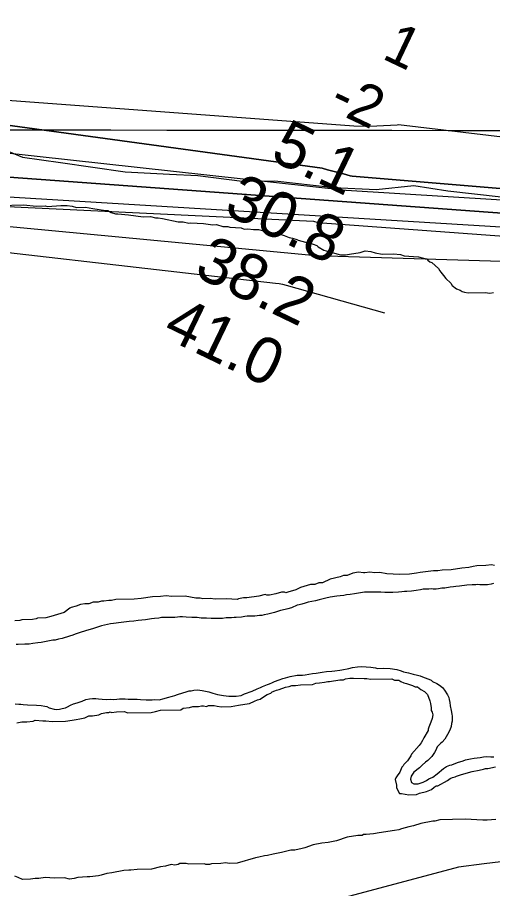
# Model space of a CAD drawing. Extents: x 3219052 to 3256913, y 800770 to 826146.
# Drawn here: x 3235776 to 3236468, y 811124 to 812391 of the extents above; entities that cross this region are included whole.
import ezdxf

# ---------------------------------------------------------------- set-up
doc = ezdxf.new("R2010")
doc.units = 0
for name, color, linetype in [('V-GRID-MAJR', 7, 'Continuous'), ('V-LEVE-TOET', 7, 'Continuous'), ('V-RIVR-EDGE', 7, 'Continuous'), ('V-RIVR-RANG', 7, 'Continuous'), ('V-SITE-VEGE', 7, 'Continuous'), ('V-TOPO-DPTH', 7, 'Continuous'), ('V-TOPO-MAJR', 7, 'Continuous'), ('V-TOPO-MINR', 7, 'Continuous'), ('V-TOPO-SHOR', 7, 'Continuous'), ('V-TOPO-WATR', 7, 'Continuous')]:
    doc.layers.add(name, color=color, linetype=linetype)

msp = doc.modelspace()

# ---------------------------------------------------------------- linework, layer by layer
at = {"layer": 'V-GRID-MAJR'}
msp.add_spline([(3223229.222, 812245.659), (3228465.955, 812237.661), (3233702.6890000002, 812230.425), (3238939.4250000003, 812223.951), (3244176.161, 812218.238), (3249412.899, 812213.287), (3254649.637, 812209.098), (3254649.6380000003, 812209.098)], degree=3, dxfattribs=at)
at = {"layer": 'V-LEVE-TOET'}
msp.add_lwpolyline([(3238182.165, 811071.7000000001), (3237860.271, 811198.746), (3237814.414, 811217.536), (3237784.448, 811226.4720000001), (3237756.583, 811232.116), (3237732.015, 811236.265), (3237708.346, 811240.419), (3237688.88, 811239.188), (3237662.825, 811237.3470000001), (3237316.042, 811205.908), (3236864.697, 811191.961), (3236556.232, 811171.966), (3236455.3140000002, 811160.1140000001), (3236418.184, 811154.96), (3236209.219, 811099.193)], dxfattribs=at)
at = {"layer": 'V-RIVR-EDGE'}
msp.add_lwpolyline([(3235755.3521574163, 812199.8585702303), (3235783.577111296, 812188.0524400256), (3235838.761683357, 812180.0917591), (3235933.054244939, 812166.8182251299), (3235997.377772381, 812163.1817380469), (3236038.6677431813, 812161.3409230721), (3236103.4141240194, 812152.9219193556), (3236150.7960151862, 812153.6741159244), (3236236.838321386, 812143.8984159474), (3236298.1212627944, 812141.1388057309), (3236352.9044780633, 812146.6541719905), (3236402.439330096, 812139.1421403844), (3236480.224931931, 812130.2562152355)], dxfattribs=at)
at = {"layer": 'V-SITE-VEGE'}
for points in [[(3235749.586, 812117.927), (3235785.686, 812118.613), (3235803.262, 812116.883), (3235816.67, 812117.139), (3235819.7830000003, 812116.166), (3235839.362, 812117.571), (3235848.648, 812117.747), (3235855.8850000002, 812116.8520000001), (3235862.113, 812114.906), (3235875.524, 812115.162), (3235885.876, 812113.2930000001), (3235904.503, 812110.552), (3235907.597, 812110.61), (3235912.8140000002, 812107.615), (3235919.042, 812105.672), (3235922.134, 812105.729), (3235937.646, 812103.962), (3235959.367, 812101.279), (3235969.68, 812101.474), (3235976.941, 812099.5480000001), (3235981.065, 812099.626), (3235987.275, 812098.711), (3236010.063, 812093.986), (3236017.284, 812094.123), (3236025.576, 812092.219), (3236028.671, 812092.278), (3236047.257, 812091.598), (3236060.7060000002, 812089.792), (3236065.863, 812089.888), (3236075.204, 812086.9720000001), (3236082.4250000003, 812087.109), (3236085.542, 812086.134), (3236102.059, 812085.417), (3236106.227, 812083.433), (3236111.384, 812083.531), (3236119.653, 812082.656), (3236126.877, 812082.794), (3236134.1350000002, 812080.8690000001), (3236157.957, 812076.162), (3236164.185, 812074.2170000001), (3236171.464, 812071.259), (3236176.6410000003, 812070.3250000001), (3236182.869, 812068.382), (3236184.952, 812067.389), (3236195.325, 812064.491), (3236203.615, 812062.584), (3236206.732, 812061.611), (3236211.926, 812059.649), (3236214.029, 812057.6240000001), (3236222.379, 812052.623), (3236225.494, 812051.65), (3236246.24, 812045.854), (3236253.461, 812045.991), (3236259.628, 812047.14), (3236275.062, 812049.497), (3236282.242, 812051.697), (3236290.5160000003, 812050.822), (3236296.744, 812048.877), (3236307.097, 812047.009), (3236323.599, 812047.324), (3236333.934, 812046.4890000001), (3236339.131, 812044.525), (3236352.558, 812043.747), (3236359.802, 812042.854), (3236367.06, 812040.926), (3236372.237, 812039.997), (3236373.306, 812037.951), (3236376.4420000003, 812035.948), (3236379.555, 812034.975), (3236389.015, 812025.868), (3236391.136, 812022.812), (3236392.205, 812020.768), (3236396.43, 812015.693), (3236399.603, 812011.6240000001), (3236406.961, 812004.5380000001), (3236409.083, 812001.484), (3236415.3680000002, 811996.446), (3236420.566, 811994.48), (3236423.699, 811992.4770000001), (3236426.812, 811991.502), (3236431.99, 811990.5700000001), (3236456.748, 811991.039), (3236463.986, 811990.1460000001), (3236469.124, 811991.277)], [(3236470.484, 811594.0430000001), (3236466.339, 811594.997), (3236458.108, 811593.807), (3236444.698, 811593.5530000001), (3236439.559, 811592.4230000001), (3236433.3910000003, 811591.274), (3236423.095, 811590.047), (3236407.664, 811587.6900000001), (3236394.253, 811587.434), (3236388.085, 811586.285), (3236381.896, 811586.1680000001), (3236362.3370000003, 811583.733), (3236357.199, 811582.6020000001), (3236346.904, 811581.376), (3236332.463, 811581.099), (3236313.875, 811581.779), (3236303.525, 811583.647), (3236296.304, 811583.508), (3236289.0640000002, 811584.403), (3236281.863, 811583.235), (3236279.801, 811583.194), (3236272.559, 811584.089), (3236264.328, 811582.899), (3236256.134, 811579.649), (3236250.977, 811579.551), (3236245.859, 811577.39), (3236231.478, 811574.0210000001), (3236220.231, 811568.647), (3236215.072, 811568.549), (3236208.924, 811566.37), (3236202.737, 811566.251), (3236188.372, 811561.85), (3236181.21, 811558.62), (3236169.924, 811555.311), (3236166.847, 811554.2170000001), (3236164.767, 811555.213), (3236160.64, 811555.133), (3236152.43, 811552.9130000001), (3236143.185, 811550.674), (3236139.056, 811550.594), (3236136.975, 811551.588), (3236127.731, 811549.3470000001), (3236110.235, 811546.953), (3236105.078, 811546.855), (3236097.877, 811545.685), (3236095.833, 811544.6140000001), (3236080.342, 811545.351), (3236063.839, 811545.0380000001), (3236056.6, 811545.931), (3236046.284, 811545.736), (3236042.139, 811546.689), (3236035.948, 811546.572), (3236020.42, 811549.372), (3236000.818, 811549.001), (3235992.5500000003, 811549.873), (3235984.3170000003, 811548.686), (3235972.972, 811548.471), (3235956.506, 811546.093), (3235946.2120000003, 811544.8640000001), (3235919.394, 811544.356), (3235913.225, 811543.2050000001), (3235909.098, 811543.127), (3235901.898, 811541.96), (3235898.805, 811541.9010000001), (3235893.667, 811540.768), (3235886.446, 811540.635), (3235880.295, 811538.454), (3235874.106, 811538.335), (3235867.938, 811537.186), (3235861.79, 811535.007), (3235854.607, 811532.805), (3235852.563, 811531.732), (3235844.431, 811525.39), (3235824.93, 811519.86), (3235817.749, 811517.66), (3235805.3710000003, 811517.425), (3235803.327, 811516.354)], [(3235803.327, 811516.354), (3235798.191, 811515.223), (3235782.718, 811514.9280000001), (3235779.644, 811513.839), (3235772.423, 811513.702)], [(3236114.1890000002, 811393.283), (3236121.349, 811396.513), (3236125.437, 811398.655), (3236129.543, 811399.765), (3236131.585, 811400.836), (3236139.74, 811406.1510000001), (3236144.858, 811408.312), (3236146.879, 811410.415), (3236150.988, 811411.525), (3236153.032, 811412.594), (3236157.1380000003, 811413.706), (3236166.362, 811416.975), (3236171.501, 811418.105), (3236175.607, 811419.215), (3236180.764, 811419.313), (3236187.964, 811420.481), (3236205.499, 811420.8150000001), (3236210.617, 811422.975), (3236215.774, 811423.074), (3236222.975, 811424.243), (3236228.111, 811425.371), (3236230.176, 811425.41), (3236245.609, 811427.768), (3236250.7660000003, 811427.866), (3236253.84, 811428.957), (3236260.011, 811430.106), (3236265.168, 811430.2050000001), (3236280.659, 811429.4670000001), (3236284.786, 811429.545), (3236289.963, 811428.611), (3236320.906, 811429.199), (3236325.072, 811427.215), (3236331.2630000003, 811427.333), (3236334.394, 811425.328), (3236338.558, 811423.346), (3236342.703, 811422.392), (3236351.014, 811419.4550000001), (3236355.18, 811417.468), (3236358.274, 811417.528), (3236363.511, 811413.4990000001), (3236368.725, 811410.505), (3236372.93, 811406.456), (3236376.2, 811397.232), (3236377.31, 811393.126), (3236378.4590000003, 811386.957), (3236378.539, 811382.8300000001), (3236379.608, 811380.7880000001), (3236380.718, 811376.68), (3236379.786, 811371.505), (3236377.8200000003, 811366.307), (3236374.865, 811359.028), (3236373.89, 811355.916), (3236373.931, 811353.851), (3236367.9390000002, 811343.419), (3236365.952, 811339.255), (3236363.949, 811336.122), (3236360.932, 811331.938), (3236349.822, 811319.3420000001), (3236348.8310000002, 811317.26), (3236346.826, 811314.126), (3236343.809, 811309.942), (3236338.75, 811304.687), (3236337.757, 811302.604), (3236335.734, 811300.503), (3236332.778, 811293.2220000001), (3236328.75, 811287.987), (3236326.745, 811284.854), (3236325.754, 811282.7710000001), (3236327.974, 811274.559), (3236328.052, 811270.432), (3236332.3340000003, 811262.258), (3236335.429, 811262.318), (3236345.7830000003, 811260.4500000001), (3236357.129, 811260.667), (3236361.215, 811262.807), (3236371.492, 811265.066), (3236378.6520000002, 811268.3), (3236382.719, 811271.4720000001), (3236385.773, 811273.5920000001), (3236387.839, 811273.633), (3236402.14, 811281.127), (3236406.207, 811284.299), (3236409.284, 811285.3910000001), (3236413.39, 811286.501), (3236415.432, 811287.572), (3236422.614, 811289.7710000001), (3236438.007, 811294.191), (3236448.282, 811296.448), (3236454.452, 811297.601), (3236457.526, 811298.6900000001), (3236460.6210000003, 811298.75), (3236471.928, 811301.027)], [(3235775.247, 811365.17), (3235782.448, 811366.34), (3235789.667, 811366.475), (3235798.932, 811367.683), (3235802.004, 811368.775), (3235813.373, 811367.958), (3235817.498, 811368.0380000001), (3235826.802, 811367.182), (3235846.399, 811367.554), (3235855.662, 811368.763), (3235861.833, 811369.912), (3235866.969, 811371.04), (3235874.17, 811372.209), (3235880.3000000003, 811375.4230000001), (3235885.4560000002, 811375.5210000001), (3235894.722, 811376.725), (3235898.807, 811378.8690000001), (3235906.008, 811380.039), (3235909.103, 811380.094), (3235911.146, 811381.167), (3235913.2290000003, 811380.176), (3235920.428, 811381.343), (3235931.776, 811381.561), (3235936.972, 811379.594), (3235971.012, 811380.242), (3235977.18, 811381.3910000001), (3235984.36, 811383.5920000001), (3236014.274, 811384.159), (3236017.329, 811386.281), (3236026.592, 811387.49), (3236031.731, 811388.62), (3236039.982, 811388.7760000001), (3236044.088, 811389.886), (3236047.183, 811389.9450000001), (3236051.328, 811388.993), (3236054.4020000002, 811390.082), (3236062.653, 811390.24), (3236066.801, 811389.286), (3236073.008, 811388.372), (3236087.451, 811388.647), (3236097.723, 811390.906), (3236106.989, 811392.112), (3236114.1890000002, 811393.283)], [(3236472.348, 811224.68), (3236459.99, 811223.412), (3236453.801, 811223.295), (3236427.9760000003, 811224.866), (3236390.841, 811224.162), (3236383.661, 811221.962), (3236380.5670000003, 811221.903), (3236363.091, 811218.474), (3236352.835, 811215.183), (3236345.634, 811214.0160000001), (3236335.375, 811210.725), (3236331.271, 811209.615), (3236325.103, 811208.466), (3236302.468, 811204.939), (3236294.237, 811203.751), (3236283.9420000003, 811202.524), (3236279.815, 811202.447), (3236277.771, 811201.375), (3236271.5840000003, 811201.257), (3236256.151, 811198.899), (3236240.776, 811193.448), (3236228.437, 811191.15), (3236219.176, 811189.941), (3236206.8370000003, 811187.644), (3236194.536, 811183.283), (3236190.43, 811182.1730000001), (3236180.1550000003, 811179.914), (3236173.966, 811179.796), (3236160.615, 811176.447), (3236148.278, 811174.149), (3236140.066, 811171.929), (3236135.9390000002, 811171.849), (3236127.727, 811169.631), (3236122.588, 811168.501), (3236095.909, 811160.772), (3236084.563, 811160.555), (3236079.386, 811161.4890000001)], [(3236079.386, 811161.4890000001), (3236072.185, 811160.317), (3236058.7770000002, 811160.0650000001), (3236055.7, 811158.978), (3236050.544, 811158.877), (3236048.461, 811159.8690000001), (3236025.769, 811159.437), (3236021.624, 811160.3910000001), (3236012.34, 811160.215), (3236010.296, 811159.144), (3236005.16, 811158.013), (3235999.983, 811158.9450000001), (3235991.768, 811156.7270000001), (3235984.569, 811155.56), (3235971.218, 811152.209), (3235950.589, 811151.818), (3235941.326, 811150.61), (3235938.231, 811150.55), (3235931.012, 811150.4130000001), (3235913.537, 811146.985), (3235906.3340000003, 811145.817), (3235898.1210000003, 811143.5970000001), (3235894.015, 811142.487), (3235881.6550000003, 811141.22), (3235877.531, 811141.142), (3235864.143, 811139.856), (3235859.004, 811138.725), (3235851.804, 811137.558), (3235844.543, 811139.483), (3235830.103, 811139.208), (3235816.674, 811139.985), (3235807.411, 811138.7760000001), (3235802.254, 811138.6780000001), (3235795.054, 811137.511), (3235783.708, 811137.294), (3235777.4590000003, 811140.2710000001), (3235772.2630000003, 811142.235)]]:
    msp.add_lwpolyline(points, dxfattribs=at)
at = {"layer": 'V-TOPO-DPTH'}
for points in [[(3237711.6959470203, 812013.2851889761), (3236978.4446943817, 812069.2369252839), (3236972.67980126, 812070.7520773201), (3235637.6560567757, 812168.0903933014), (3235630.8095992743, 812168.954961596), (3235623.973784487, 812169.9111963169), (3235617.340974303, 812170.906967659), (3235607.1922265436, 812172.3974644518), (3235597.0374562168, 812173.8447153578), (3235586.873652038, 812175.2270974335), (3235576.7038252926, 812176.5662336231), (3234974.3108995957, 812244.8412438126), (3234948.2321198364, 812247.113933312), (3234922.1547592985, 812249.4029973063), (3234868.502054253, 812254.1380784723), (3234815.6183309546, 812258.9957155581), (3234762.7598384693, 812264.104991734), (3234709.9391922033, 812269.5917265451), (3234657.143776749, 812275.3301004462), (3234408.9824128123, 812303.2001529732)], [(3238279.0662157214, 811992.5104605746), (3236263.3109329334, 812160.2666766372), (3236260.2639892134, 812160.9932020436), (3236250.7748997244, 812163.6124412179), (3236242.9930151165, 812165.730966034), (3236235.2014788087, 812167.8128518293), (3236227.3954649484, 812169.8397790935), (3236219.5797993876, 812171.8300673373), (3235701.0112393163, 812242.9258117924)], [(3235701.0112393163, 812242.9258117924), (3236219.5797993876, 812171.8300673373), (3236227.3954649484, 812169.8397790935), (3236235.2014788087, 812167.8128518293), (3236242.9930151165, 812165.730966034), (3236250.7748997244, 812163.6124412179), (3236260.2639892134, 812160.9932020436), (3236263.3109329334, 812160.2666766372), (3238476.978607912, 811976.0396943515)]]:
    msp.add_lwpolyline(points, dxfattribs=at)
at = {"layer": 'V-TOPO-MAJR'}
msp.add_lwpolyline([(3235585.3704309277, 812103.9168314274), (3236210.408453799, 812045.0384253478), (3236877.8816674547, 812024.6945316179), (3236883.372915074, 812024.502033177), (3236888.8262861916, 812023.830021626), (3236894.2544063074, 812022.8383346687), (3236933.0393715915, 812013.9773542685), (3236943.9681957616, 812011.4430090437), (3236954.8856486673, 812008.8612680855), (3236965.786044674, 812006.2084335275), (3236976.675069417, 812003.5082032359), (3237637.9890776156, 811937.6883757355)], dxfattribs=at)
at = {"layer": 'V-TOPO-MINR'}
for points in [[(3234430.0256441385, 812363.2484721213), (3235014.625049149, 812391.2791421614), (3235015.10351626, 812391.3047767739), (3235016.9311097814, 812391.3300911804), (3235017.4268970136, 812391.2858917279), (3235017.5909552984, 812391.2598474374), (3235055.2225959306, 812384.4319179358), (3235074.202504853, 812380.9905720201), (3235093.182972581, 812377.5523130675), (3235112.1642785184, 812374.118684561), (3235634.783277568, 812279.7305905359), (3235637.677363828, 812279.3185897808), (3235642.425527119, 812279.2395690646), (3235643.48957829, 812279.4625913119), (3236265.9415057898, 812233.7821427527), (3236282.6928479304, 812233.3282800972), (3236299.492951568, 812233.657322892), (3236328.688809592, 812235.2577443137), (3236330.8262788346, 812235.612818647), (3237034.8478958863, 812152.3173607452), (3237042.4332785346, 812150.4810922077), (3237070.4625623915, 812144.2142284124), (3238468.788826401, 811995.0523872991)], [(3234408.9824128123, 812303.2001529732), (3234657.143776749, 812275.3301004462), (3234709.9391922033, 812269.5917265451), (3234762.7598384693, 812264.104991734), (3234815.6183309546, 812258.9957155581), (3234868.502054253, 812254.1380784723), (3234922.1547592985, 812249.4029973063), (3234948.2321198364, 812247.113933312), (3234974.3108995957, 812244.8412438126), (3235576.7038252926, 812176.5662336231), (3235586.873652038, 812175.2270974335), (3235597.0374562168, 812173.8447153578), (3235607.1922265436, 812172.3974644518), (3235617.340974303, 812170.906967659), (3235623.973784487, 812169.9111963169), (3235630.8095992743, 812168.954961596), (3235637.6560567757, 812168.0903933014), (3236972.67980126, 812070.7520773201), (3236978.4446943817, 812069.2369252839), (3237711.6959470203, 812013.2851889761)], [(3234389.5547021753, 812289.0833983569), (3234839.3901921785, 812230.3752246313), (3234860.4491929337, 812227.7203740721), (3234881.522412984, 812225.188400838), (3234902.6169619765, 812222.8407435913), (3234923.7257302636, 812220.6159636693), (3234944.851145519, 812218.5494723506), (3234965.9845341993, 812216.5711254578), (3235558.795259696, 812151.487020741), (3235587.044893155, 812147.1051769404), (3235615.253882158, 812142.4688761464), (3235643.435774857, 812137.662937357), (3236942.230676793, 812058.3951681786), (3237652.881814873, 811987.293061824)], [(3234434.962991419, 812252.6385372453), (3234464.5223465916, 812249.2440999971), (3234494.0648566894, 812245.7127790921), (3234523.582099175, 812241.9761327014), (3234553.0824965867, 812238.1026026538), (3234940.5309824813, 812185.8580709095), (3234948.4701514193, 812184.853397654), (3234956.4185995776, 812183.9352381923), (3234964.3809665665, 812183.1468494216), (3234972.352612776, 812182.4449744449), (3234987.958356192, 812181.1991342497), (3235003.746365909, 812180.0591836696), (3235545.818580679, 812130.5743479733), (3235562.250964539, 812127.8017561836), (3235578.6617078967, 812124.9101439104), (3236207.163922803, 812094.8384156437), (3236213.1819288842, 812092.9794959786), (3236920.467636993, 812041.1775389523), (3236943.0259246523, 812035.7495556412), (3238400.420479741, 811879.8452404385)], [(3235500.165579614, 812223.0232822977), (3236254.4273411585, 812139.8911612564), (3236997.09637252, 812094.0140207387), (3237011.1573744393, 812091.5697970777), (3237025.2740428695, 812089.4185243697), (3238493.201968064, 811953.2482152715)], [(3235559.9791991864, 812072.6300867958), (3236151.792986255, 812004.7017733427)], [(3236151.792986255, 812004.7017733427), (3236157.0029839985, 812004.0793555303), (3236162.154444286, 812003.082391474), (3236167.2668796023, 812001.8357299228), (3236310.4037004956, 811961.390719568)]]:
    msp.add_lwpolyline(points, dxfattribs=at)
at = {"layer": 'V-TOPO-SHOR'}
for points in [[(3236469.089, 811567.703), (3236465.673, 811566.78), (3236460.539, 811565.823), (3236454.96, 811565.719), (3236449.373, 811566.04), (3236446.361, 811566.4130000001), (3236443.364, 811565.9280000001), (3236438.216, 811565.829), (3236430.499, 811565.2540000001), (3236419.794, 811563.761), (3236414.221, 811563.226), (3236410.789, 811563.161), (3236406.076, 811562.643), (3236398.376, 811561.207), (3236393.6550000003, 811561.1190000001), (3236388.951, 811560.171), (3236385.525, 811559.675), (3236381.234, 811559.593), (3236378.222, 811559.966), (3236374.795, 811559.47), (3236366.642, 811559.317), (3236362.788, 811558.8150000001), (3236356.367, 811557.834), (3236349.947, 811556.853), (3236343.086, 811556.294), (3236339.654, 811556.226), (3236335.799, 811555.725), (3236330.659, 811555.198), (3236322.512, 811554.612), (3236318.649, 811554.541), (3236315.2090000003, 811554.903), (3236310.916, 811554.821), (3236304.899, 811555.137), (3236299.75, 811555.0380000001), (3236296.308, 811555.403), (3236293.303, 811555.346), (3236289.443, 811555.274), (3236284.292, 811555.176)], [(3236284.292, 811555.176), (3236281.288, 811555.118), (3236275.725, 811554.154), (3236272.7290000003, 811553.666), (3236266.737, 811552.693), (3236260.316, 811551.715), (3236255.174, 811551.186), (3236251.327, 811550.2540000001), (3236245.757, 811549.72), (3236241.044, 811549.202), (3236231.198, 811547.725), (3236225.213, 811546.324), (3236219.2290000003, 811544.921), (3236215.383, 811543.9890000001), (3236209.829, 811542.5970000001), (3236199.562, 811540.684), (3236194.866, 811539.308), (3236190.168, 811537.929), (3236186.332, 811536.5700000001), (3236183.336, 811536.082), (3236175.2460000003, 811532.4940000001), (3236169.6920000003, 811531.101), (3236165.846, 811530.17), (3236159.012, 811528.322), (3236150.478, 811525.584), (3236140.647, 811523.2490000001), (3236135.5130000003, 811522.295), (3236132.097, 811521.3690000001), (3236128.665, 811521.306), (3236121.8140000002, 811520.317), (3236118.81, 811520.259), (3236115.375, 811520.194), (3236110.654, 811520.104), (3236107.23, 811519.61), (3236102.096, 811518.654), (3236094.801, 811518.514), (3236091.796, 811518.457), (3236087.9420000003, 811517.9550000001), (3236084.938, 811517.898), (3236080.217, 811517.808), (3236074.6550000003, 811516.843), (3236067.788, 811516.712), (3236063.917, 811517.069), (3236058.338, 811516.962), (3236051.463, 811517.261), (3236043.73, 811517.544), (3236037.705, 811518.287), (3236034.7, 811518.232), (3236029.982, 811518.142), (3236021.81, 811518.844), (3236016.651, 811519.176), (3236012.789, 811519.1020000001), (3236009.356, 811519.037), (3236005.502, 811518.535), (3235999.4930000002, 811518.42), (3235989.194, 811518.224), (3235985.759, 811518.158), (3235981.913, 811517.226), (3235975.914, 811516.684), (3235971.2, 811516.165), (3235962.633, 811515.143), (3235951.9220000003, 811514.0800000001), (3235945.502, 811513.1), (3235938.643, 811512.54), (3235927.08, 811511.033), (3235915.9450000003, 811509.534), (3235911.663, 811509.022), (3235903.11, 811507.144), (3235898.4080000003, 811506.196), (3235886.886, 811502.54), (3235875.362, 811498.886), (3235867.678, 811496.595), (3235860.432, 811493.881), (3235857.024, 811492.527), (3235851.898, 811491.143), (3235841.2260000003, 811487.936), (3235836.091, 811486.9770000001), (3235830.965, 811485.593), (3235827.963, 811485.535), (3235820.699, 811483.68), (3235810.852, 811482.2050000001), (3235805.711, 811481.677), (3235798.861, 811480.6900000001), (3235793.298, 811479.725), (3235786.86, 811479.6020000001), (3235777.426, 811478.9940000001), (3235774.4220000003, 811478.937)], [(3235950.239, 811399.421), (3235955.396, 811399.089), (3235963.565, 811398.387), (3235967.43, 811398.461), (3235972.15, 811398.551), (3235976.005, 811399.0530000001), (3235982.45, 811398.745), (3235989.714, 811400.601), (3235994.41, 811401.9770000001), (3236002.1, 811403.841), (3236005.088, 811404.756), (3236009.348, 811406.554), (3236017.032, 811408.848), (3236021.728, 811410.224), (3236025.9960000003, 811411.594), (3236029.001, 811411.652), (3236032.847, 811412.584), (3236038.417, 811413.118), (3236045.309, 811411.961), (3236050.046, 811411.193), (3236054.7830000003, 811410.4230000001), (3236060.403, 811408.383), (3236067.311, 811406.368), (3236070.321, 811405.997), (3236076.355, 811404.824), (3236083.674, 811403.675), (3236094.404, 811403.88), (3236101.684, 811404.875), (3236106.794, 811407.12), (3236117.878, 811411.193), (3236125.115, 811414.337), (3236129.795, 811416.573), (3236132.7770000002, 811417.917), (3236140.015, 811421.06), (3236143.003, 811421.976), (3236147.2600000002, 811423.774), (3236150.24, 811425.1190000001), (3236157.058, 811427.8250000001), (3236162.6040000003, 811429.648), (3236166.45, 811430.579), (3236173.284, 811432.427), (3236183.553, 811434.338), (3236191.278, 811434.485), (3236195.132, 811434.9890000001), (3236200.265, 811435.943), (3236205.827, 811436.908), (3236210.97, 811437.434), (3236219.528, 811438.886), (3236225.951, 811439.867), (3236233.668, 811440.443), (3236237.95, 811440.9550000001), (3236245.231, 811441.952), (3236248.235, 811442.007), (3236258.4930000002, 811444.348), (3236264.048, 811445.743), (3236271.326, 811446.74), (3236276.899, 811447.275), (3236290.6550000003, 811446.2490000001), (3236297.119, 811445.083), (3236300.137, 811444.283), (3236309.5810000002, 811444.463), (3236318.6, 811444.2050000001), (3236328.504, 811442.675), (3236334.552, 811440.643), (3236338.011, 811439.421), (3236345.339, 811437.844), (3236352.247, 811435.828), (3236358.286, 811434.2270000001), (3236362.165, 811433.4400000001), (3236368.223, 811430.981), (3236375.139, 811428.536), (3236378.168, 811427.305), (3236380.3540000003, 811425.199), (3236386.42, 811422.31), (3236390.3310000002, 811419.809), (3236394.687, 811416.456), (3236397.7660000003, 811412.6510000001), (3236402.187, 811405.866), (3236403.977, 811402.036), (3236404.465, 811399.04), (3236405.4050000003, 811394.7660000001), (3236405.923, 811390.054), (3236407.34, 811383.211), (3236408.305, 811377.649), (3236408.792, 811374.653), (3236408.858, 811371.218), (3236408.929, 811367.356), (3236408.129, 811364.337), (3236407.361, 811359.6), (3236405.313, 811354.408), (3236402.003, 811347.906), (3236398.261, 811341.393), (3236394.481, 811337.029), (3236391.947, 811334.833), (3236386.887, 811330.0160000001), (3236385.261, 811325.261), (3236383.18, 811321.7880000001), (3236379.424, 811316.135), (3236373.519, 811310.442), (3236370.136, 811307.802), (3236365.497, 811303.421)], [(3235773.058, 811392.618), (3235778.217, 811392.2880000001), (3235781.221, 811392.343), (3235784.67, 811391.551), (3235790.687, 811391.235), (3235804.007, 811390.6290000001), (3235810.883, 811390.332), (3235816.056, 811389.142), (3235819.068, 811388.77), (3235822.536, 811387.1190000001), (3235829.872, 811385.112), (3235833.3200000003, 811384.319), (3235837.605, 811384.829), (3235841.443, 811386.189), (3235846.147, 811387.137), (3235849.127, 811388.483), (3235853.377, 811390.711), (3235857.636, 811392.509), (3235863.182, 811394.332), (3235866.17, 811395.247), (3235870.438, 811396.615), (3235875.9760000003, 811398.868), (3235881.111, 811399.8250000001), (3235885.393, 811400.335), (3235890.114, 811400.425), (3235893.984, 811400.068), (3235899.579, 811399.317), (3235906.026, 811399.01), (3235911.167, 811399.5380000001), (3235916.326, 811399.206), (3235921.0470000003, 811399.294), (3235924.901, 811399.7980000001), (3235929.191, 811399.88), (3235933.056, 811399.954), (3235937.355, 811399.605), (3235945.5160000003, 811399.331), (3235950.239, 811399.421)], [(3236365.497, 811303.421), (3236361.278, 811299.4770000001), (3236353.238, 811293.312), (3236349.054, 811287.652), (3236348.286, 811282.915), (3236349.662, 811278.218), (3236353.136, 811276.14), (3236359.572, 811276.261), (3236366.829, 811278.544), (3236371.5, 811281.211), (3236374.894, 811283.42), (3236380.8510000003, 811286.109), (3236387.2, 811290.9550000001), (3236396.502, 811298.4280000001), (3236400.737, 811301.514), (3236405.417, 811303.751), (3236408.413, 811304.236), (3236416.511, 811307.3960000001), (3236425.053, 811309.704), (3236428.461, 811311.056), (3236435.725, 811312.914), (3236440.858, 811313.868), (3236449.8540000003, 811314.898), (3236454.5670000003, 811315.4180000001), (3236458.8510000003, 811315.9280000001), (3236465.296, 811315.621), (3236469.589, 811315.703)]]:
    msp.add_lwpolyline(points, dxfattribs=at)
at = {"layer": 'V-TOPO-WATR'}
msp.add_lwpolyline([(3235701.0112393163, 812242.9258117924), (3236219.5797993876, 812171.8300673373), (3236227.3954649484, 812169.8397790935), (3236235.2014788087, 812167.8128518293), (3236242.9930151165, 812165.730966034), (3236250.7748997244, 812163.6124412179), (3236260.2639892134, 812160.9932020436), (3236263.3109329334, 812160.2666766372), (3238476.978607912, 811976.0396943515)], dxfattribs=at)

# ---------------------------------------------------------------- texts
at = {"layer": 'V-RIVR-RANG'}
for s, height, rotation, p in [('1', 60, 334.56072222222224, (3236305.1146007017, 812332.3317325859)), ('-2', 60, 334.56072222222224, (3236227.1669656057, 812258.6732640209)), ('5.1', 67, 334.27832571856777, (3236142.135738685, 812185.0065992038)), ('30.8', 67, 334.27832571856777, (3236074.2439310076, 812106.7145497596)), ('38.2', 67, 334.27832571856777, (3236031.0659310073, 812016.5165497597)), ('41.0', 67, 334.27832571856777, (3235985.274864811, 811927.5768329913))]:
    msp.add_text(s, height=height, rotation=rotation, dxfattribs=at).set_placement(p)

doc.saveas('drawing.dxf')
